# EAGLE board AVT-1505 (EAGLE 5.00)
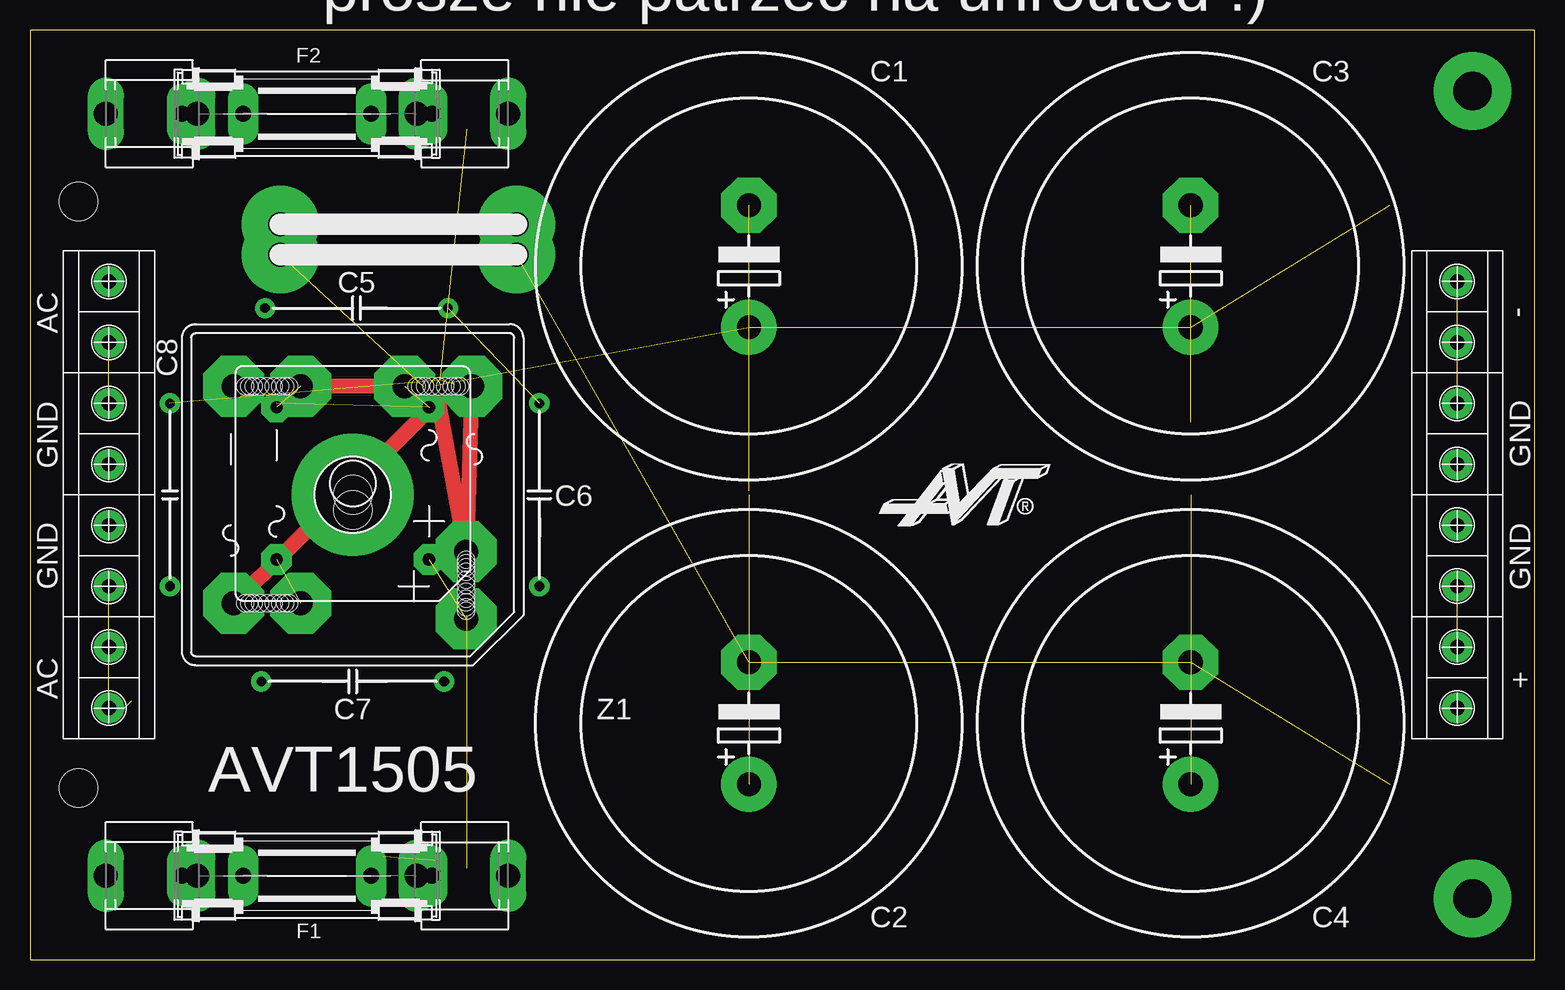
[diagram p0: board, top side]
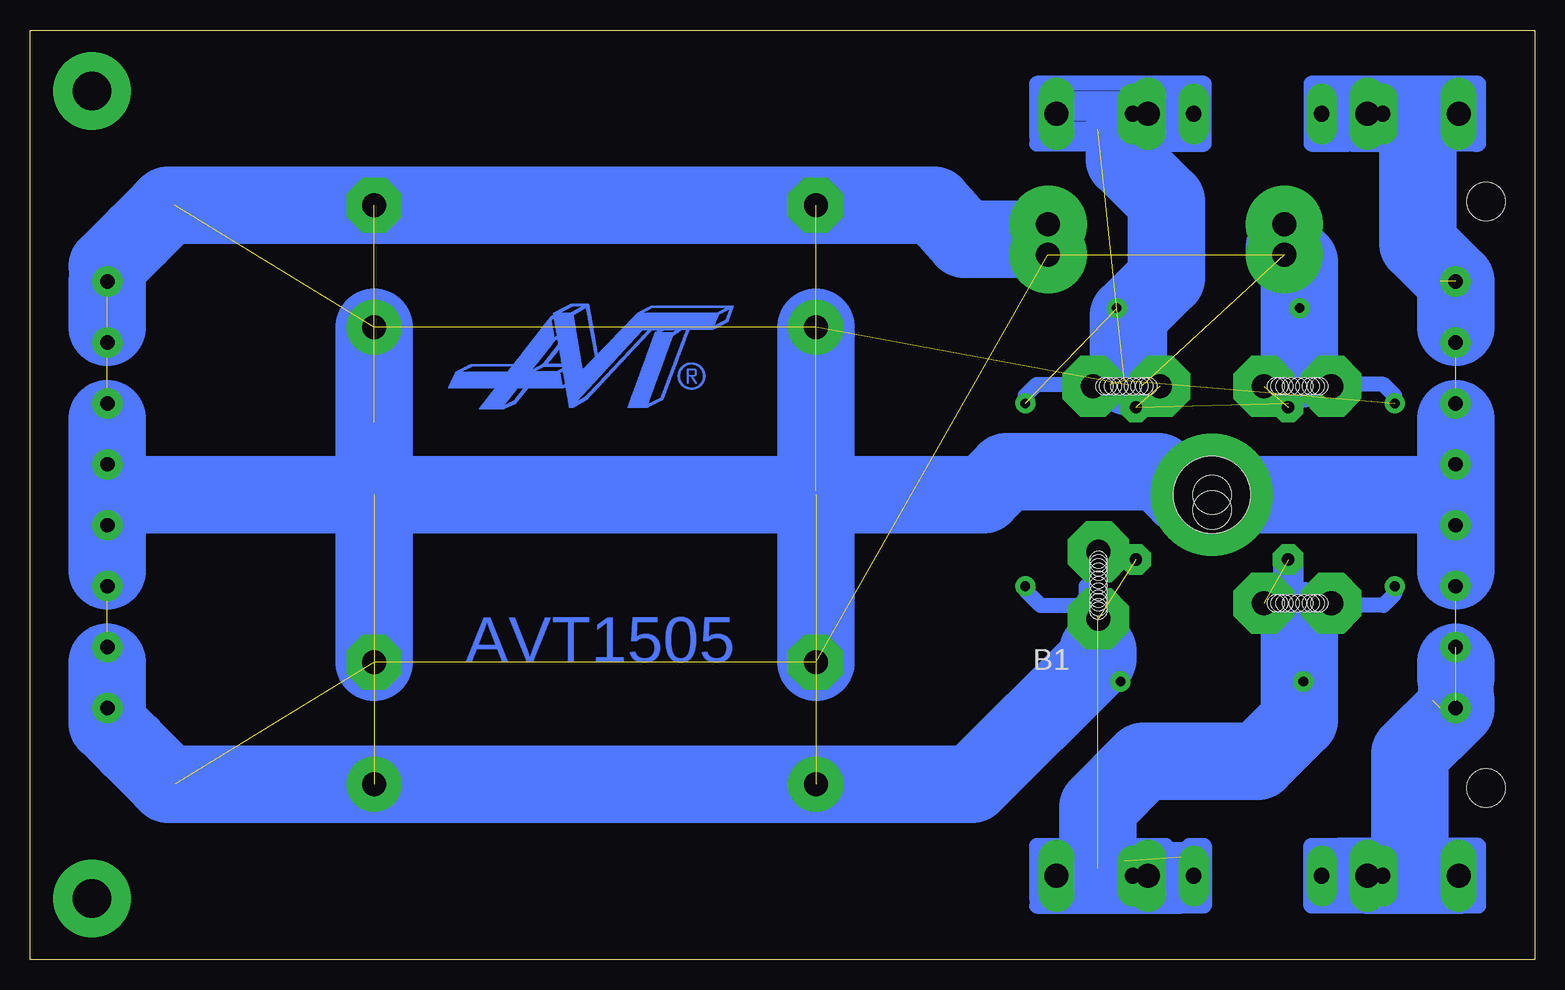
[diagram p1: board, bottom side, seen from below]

Size 125.43 x 77.46 mm. Coordinates in mm from the lower left corner, seen from the top.
Outline: 0,0 125.43,0 125.43,77.46 0,77.46 0,0
Copper layers (1*16): Top 0.035mm / dielectric 1.5mm / Bottom 0.035mm
Design rules "default": minimum track width 10mil, minimum drill 24mil, track to track 8mil, track to pad 8mil, pad to pad 8mil, via to via 8mil, smd to smd 8mil, copper to edge 40mil, drill to drill 8mil, minimum pad ring 10mil, minimum via ring 8mil, stop-mask expansion 4mil, vias tented up to drill 0mil, thermal gap 10mil
Holes 3.2 mm at 26.9,38.73 26.9,37.46 4.04,63.18 4.04,14.28

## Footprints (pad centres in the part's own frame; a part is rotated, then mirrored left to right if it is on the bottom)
B25A- = drill 2.007 pad 5.08 octagon: + -10.338,9.449; +1 -4.75,9.449; - 9.042,-4.343; -1 9.042,-9.931; AC1 9.042,4.343; AC1- 9.042,9.931; AC2 -9.042,-4.343; AC2- -9.042,-9.931 | hole 6.401: 0,0 | hole 1.4: -8.652,9.446; -6.429,9.446; -7.541,9.446; -9.366,9.446; -5.715,9.446; -6.032,9.446; -7.064,9.446; -8.096,9.446; -8.969,9.446; -5.397,9.446; -9.684,9.446; -9.049,-6.032; -9.049,-8.255; -9.049,-7.144; -9.049,-5.318; -9.049,-8.969; -9.049,-8.652; -9.049,-7.699; -9.049,-6.588; -9.049,-5.636; 9.049,-8.255; 9.049,-6.032; 9.049,-7.144; 9.049,-8.969; 9.049,-5.318; 9.049,-5.636; 9.049,-6.588; 9.049,-7.699; 9.049,-8.652; 9.049,6.032; 9.049,8.255; 9.049,7.144; 9.049,8.969; 9.049,5.318; 9.049,8.652; 9.049,7.699; 9.049,6.588; 9.049,5.636
GBPC8 = drill 1.016 pad 2.54 octagon: + 6.35,6.35; - -6.35,-6.35; AC1 -6.35,6.35; AC2 6.35,-6.35
EB35D = drill 2.007 pad 4.597 round: + -5.08,0 | drill 2.007 pad 4.597 octagon: - 5.08,0
SH32 = drill 2.007 long: 1A -16.764,0; 1B -9.144,0; 2A 9.144,0; 2B 16.764,0
SHK20L = drill 1.321 pad 2.54 long: 1A -10.414,0; 1B -5.334,0; 2A 10.414,0; 2B 5.334,0
ARK2 = drill 1.2 pad 2.54 round: 1 -2.54,0; 3 2.54,0 | drill 0.8 pad 2.54 round: 2 2.54,0

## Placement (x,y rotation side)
B1  [B25A-]  26.9,38.73 90 bottom
B2  [GBPC8]  26.9,39.68 270 top
C1  [EB35D]  59.92,57.78 90 top
C2  [EB35D]  59.92,19.68 90 top
C3  [EB35D]  96.75,57.78 90 top
C4  [EB35D]  96.75,19.68 90 top
F1  [SH32]  23.09,6.98 0 top
F2  [SH32]  23.09,70.48 0 top
F3  [SHK20L]  23.09,6.98 0 top
F4  [SHK20L]  23.09,70.48 0 top
U$1  ARK2  [ARK2]  6.58,33.65 90 top
U$2  ARK2  [ARK2]  6.58,43.81 90 top
U$5  ARK2  [ARK2]  6.58,23.49 90 top
U$6  ARK2  [ARK2]  6.58,53.97 90 top

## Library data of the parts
B1 B2 = rectifier
C1-C4 = rcl
F1-F4 = fuse
U$1 U$2 U$5 U$6 = ark2

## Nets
N$1: F1.1A U$5.1 U$5.2
N$2: F2.1A U$6.1 U$6.2
N$4: B1.AC1- F1.2A
N$10: B1.AC1 B2.AC1
N$11: B1.+1 B1.-1 C1.+ C1.- C2.+ C2.- C3.+ C3.- C4.+ C4.- U$1.1 U$1.2 U$2.1 U$2.2
N$22: B1.AC2 B2.AC2
N$23: B1.- B2.-
N$24: B1.+ B2.+
N$33: B1.AC2- F2.2A

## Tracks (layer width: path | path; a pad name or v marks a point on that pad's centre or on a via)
N$1  (1 unrouted)
  Bottom 1.27: F1.1A 9.76,6.98 9.76,7.62 10.39,8.25
  Bottom 6.452: 10.39,8.25 10.39,17.14 U$5.1 6.58,21.59
N$2  (4 unrouted)
  Bottom 1.27: F2.1A 6.58,70.48 6.58,69.84 9.76,69.84 | 4.04,55.24 4.04,56.51 | 4.04,55.24 4.04,53.97 U$6.1 | 5.31,46.35 arc-90 6.58,47.62 | 5.31,46.35 arc90 6.58,45.08 arc90 7.85,46.35 | 6.58,47.62 arc-90 7.85,46.35 | 5.31,46.35 arc-90 6.58,47.62 | 6.58,50.16 arc90 7.85,51.43 arc90 6.58,52.7 arc90 5.31,51.43 arc90 6.58,50.16 | 7.85,31.11 arc-90 6.58,29.84 arc-90 5.31,31.11 | 5.31,31.11 arc-90 6.58,32.38 arc-90 7.85,31.11 | 6.58,24.76 arc-90 5.31,26.03 arc-90 6.58,27.3 | 6.58,24.76 arc90 7.85,26.03 arc90 6.58,27.3 | 4.04,55.24 4.04,52.7 6.58,50.16 | 6.58,50.16 9.12,52.7 9.12,55.88 | 6.58,27.3 4.04,24.76 4.04,20.32 8.49,20.32 8.49,21.59 9.12,22.22 9.12,24.76 6.58,27.3 | 6.58,27.3 6.58,26.03 4.68,24.12 8.49,24.12 7.85,24.76 6.58,24.76 | 6.58,24.76 4.68,24.76 | 5.31,31.11 5.95,31.11 | 5.31,31.11 5.31,46.35 | 5.31,46.35 7.85,46.35 | 7.85,46.35 7.85,31.11 | 7.85,56.51 arc90 6.58,57.78 arc90 5.31,56.51 arc90 6.58,55.24 arc90 7.85,56.51 | 5.31,20.95 arc90 6.58,19.68 arc90 7.85,20.95 arc90 6.58,22.22 arc90 5.31,20.95
  Bottom 6.452: 9.76,69.84 9.76,59.69 U$6.2 6.58,52.7 | 6.58,24.76 6.58,23.49 | 6.58,32.38 6.58,45.08
N$3
  Bottom 1.27: 5.31,72.38 14.2,72.38 14.2,71.11 | 14.2,71.11 14.2,71.75 | 14.2,69.21 14.2,71.11 | 14.2,69.21 14.2,68.57 | 14.2,69.21 14.2,70.48 13.57,70.48 | 14.2,69.21 13.57,69.21 13.57,70.48 | 13.57,70.48 13.57,71.11 | 13.57,70.48 13.57,69.84 | 13.57,70.48 13.57,71.75 14.84,71.75 14.84,67.94 15.31,67.94 | 15.31,67.94 15.47,67.94 | 15.47,67.94 15.47,73.02 13.57,73.02 | 13.57,73.02 4.68,73.02 4.68,67.94 5.07,67.94 | 5.07,67.94 6.58,67.94 | 4.99,68.1 5.07,68.1 5.07,67.94 | 5.07,67.94 15.31,67.94 | 15.31,67.94 12.77,67.94 12.77,71.99 5.55,71.99 5.55,71.27 7.06,71.27 7.06,68.73 | 13.57,73.02 18.65,73.02 18.65,67.94 15.47,67.94 | 15.47,67.94 16.42,67.94 16.42,72.7 17.38,72.7 | 17.69,72.7 17.38,72.7 | 17.38,72.7 17.38,68.26
N$4  (via drill 0.6)  (1 unrouted)
  Top 1.27: B1.AC1- v36.27,29.69
  Bottom 1.27: F1.2A 35.79,6.98 36.43,7.62 | 36.43,29.84 v36.27,29.69 36.43,29.2 36.43,28.57
  Bottom 6.452: 36.43,7.62 36.43,12.7 32.62,16.5 23.09,16.5 19.6,20 19.6,28.25
N$6
  Bottom 1.27: 32.62,73.02 31.35,73.02 | 32.62,73.02 41.51,73.02 41.51,71.75 | 41.51,69.21 41.51,70.48 | 41.51,68.57 41.51,69.21 | 41.51,68.57 41.51,67.94 34.2,67.94 31.03,67.94 | 31.03,67.94 30.71,67.94 30.71,68.57 | 30.71,69.21 30.71,70.48 | 30.71,73.02 30.71,71.75 | 30.71,71.75 41.51,71.75 | 41.51,70.48 41.51,71.75 | 30.71,70.48 41.51,70.48 | 30.71,70.48 30.71,71.75 | 30.71,73.02 32.62,73.02 | 30.71,69.21 30.71,73.02 | 30.71,69.21 41.51,69.21 | 30.71,68.57 30.71,69.21 | 30.71,68.57 31.98,68.57 | 31.98,68.57 41.51,68.57 | 31.98,68.57 32.3,68.57 32.3,68.26 31.03,68.26 31.03,67.94 | 31.03,67.94 27.54,67.94 27.54,73.02 30.71,73.02 | 30.71,73.02 29.76,73.02 29.76,68.26 28.81,68.26 | 28.49,68.26 28.81,68.26 | 28.81,68.26 28.81,72.38
  Bottom 6.452: 33.89,48.57 33.89,53.65 30.71,56.83 30.71,63.18 34.2,66.67 34.2,67.94
N$7
  Bottom 1.27: 7.85,72.38 6.58,72.38 6.58,69.21
N$9  (via drill 0.8 pad 1.68)
  other vias: 19.28,23.17
N$10  (2 unrouted)
N$11  (via drill 0.6, 1.2 pad 2.54, 2 pad 6.45, 3.2 pad 10.16)  (13 unrouted)
  Top 1.27: B1.+1 v33.81,47.86 | v32.77,47.79 B1.-1
  Bottom 1.27: 6.58,38.73 9.12,38.73 | 7.85,41.27 U$2.1 5.95,40.63 5.95,36.19 | 8.49,36.19 9.76,36.19 | 8.49,36.19 10.39,36.19 | 7.85,36.19 8.49,36.19 | 7.85,41.27 5.31,41.27 | 7.85,41.27 9.12,41.27 | 5.31,36.19 5.31,41.27 | U$1.2 5.95,36.19 | U$1.2 7.85,36.19 | 5.31,41.27 arc-90 6.58,42.54 | 7.85,41.27 arc90 6.58,42.54 | 5.95,36.19 5.31,36.19 | 5.31,36.19 arc90 6.58,34.92 arc90 7.85,36.19 | U$1.1 U$1.2 | 6.58,42.54 U$2.2
  Bottom 2.54: U$1.2 6.58,38.73 U$2.1
  Bottom 3.81: 118.98,52.7 v118.98,51.43 | v118.98,56.51 118.98,57.78 118.98,59.05 | v118.98,26.03 v118.98,20.95 118.98,19.68 118.98,18.41
  Bottom 6.452: 113.37,62.86 arc-45 114.27,62.49 116.44,60.32 | 116.44,60.32 118.98,57.78 | v118.98,56.51 118.98,52.7 | 96.75,38.73 96.75,42.22 | 59.92,38.73 59.92,39.05 | 59.92,38.73 96.75,38.73 | 58.97,38.73 45.95,38.73 44.05,40.63 31.35,40.63 29.44,38.73 v26.9,38.73 9.12,38.73 | 58.97,38.73 59.92,38.73 | 96.75,38.73 111.99,38.73 | 111.99,38.73 115.17,38.73 | 111.99,38.73 117.71,38.73 | 58.97,38.73 59.6,39.37 59.92,39.05 | 113.37,14.6 arc45 114.27,14.97 117.07,17.77 | 117.07,17.77 118.98,19.68 | 59.92,39.05 59.92,33.33 | 59.92,33.33 C2.- | 87.86,14.6 C2.+ 51.35,14.6 | 87.86,14.6 89.45,14.6 | 87.86,14.6 113.9,14.6 117.07,17.77 | C4.- 96.75,42.22 | 96.75,42.22 96.75,44.76 | C1.+ 59.92,33.33 | C3.+ 96.75,42.22 | 116.44,60.32 113.9,62.86 C3.- C1.- 56.75,62.86 | 56.75,62.86 55.16,62.86 | 42.14,60 47.54,60 50.08,62.86 56.75,62.86
  other vias: 20.87,58.73 40.55,58.73 20.87,61.27 40.55,61.27
N$12  (via drill 1.2 pad 2.54)
  Bottom 3.81: v118.98,36.19 v118.98,41.27
N$13  (2 unrouted)
  Bottom 1.27: 117.71,56.51 arc-90 118.98,57.78 | 117.71,56.51 arc-90 118.98,57.78 | 117.71,56.51 arc90 118.98,55.24 arc90 120.25,56.51 arc90 118.98,57.78 | 117.71,46.35 arc-90 118.98,47.62 arc-90 120.25,46.35 arc-90 118.98,45.08 arc-90 117.71,46.35 | 117.71,51.43 arc-90 118.98,52.7 arc-90 120.25,51.43 arc-90 118.98,50.16 arc-90 117.71,51.43
N$15
  Bottom 1.27: 118.34,41.27 arc-90 118.98,42.54 arc-90 120.25,41.27 arc-90 118.98,40 arc-90 118.34,41.27
N$17
  Bottom 1.27: 113.9,38.73 arc-90 112.63,40 arc-90 113.9,38.73
N$18  (1 unrouted)
  Bottom 1.27: 117.71,31.11 arc-90 118.98,32.38 arc-90 120.25,31.11 arc-90 118.98,29.84 arc-90 117.71,31.11 | 117.71,20.95 arc-90 118.98,22.22 arc-90 120.25,20.95 arc-90 118.98,19.68 arc-90 117.71,20.95 | 118.98,24.76 arc90 120.25,26.03 arc90 118.98,27.3 arc90 117.71,26.03 arc90 118.98,24.76
  Bottom 6.452: 118.98,19.68 118.98,24.76
N$19
  Bottom 1.27: 5.95,68.57 5.95,71.11
N$20
  Bottom 1.27: 5.15,6.35 5.87,6.35 5.87,5.47 14.2,5.47 14.2,5.55 | 5.95,9.52 5.31,9.52 | 5.95,9.52 15.47,9.52 | 15.47,9.52 15.47,4.44 15.15,4.44 | 14.2,4.44 15.15,4.44 | 14.2,4.44 4.68,4.44 4.68,9.52 5.95,9.52 | 5.95,9.52 14.2,9.52 14.2,8.25 | 14.2,8.25 14.2,6.98 | 14.2,4.44 5.95,4.44 5.95,8.25 | 5.95,9.52 5.95,8.25 | 5.95,8.25 14.2,8.25 | 14.2,8.25 6.58,8.25 6.58,6.98 | 6.58,6.35 6.58,5.08 | 14.2,4.44 14.2,5.55 | 14.2,5.55 14.2,6.35 | 14.2,6.35 14.2,6.98 | 14.2,6.98 6.58,6.98 | 6.58,6.35 6.58,6.98 | 14.2,6.35 6.58,6.35 | 14.2,5.55 14.52,5.55 14.52,7.22 | 15.15,4.44 17.38,4.44 | 17.38,4.44 18.65,4.44 18.65,9.52 15.47,9.52 | 15.47,9.52 16.42,9.52 16.42,4.76 17.38,4.76 17.38,4.44 | 17.38,4.44 17.38,8.88
N$21  (via drill 1.2 pad 2.54)
  Bottom 3.81: v118.98,31.11 118.98,32.38 | 118.98,45.08 v118.98,46.35
  Bottom 6.452: 118.98,32.38 118.98,45.08
N$22  (1 unrouted)
  Bottom 2.54: 20.23,29.2 20.23,29.84 20.55,30.16 B2.AC2
N$23  (1 unrouted)
N$24  (1 unrouted)
N$25  (1 unrouted)
  Bottom 0.406: 33.57,8.57 30.08,8.57 29.44,7.93
  Bottom 1.27: 31.03,9.2 28.81,9.2 28.81,9.52 27.54,9.52 27.54,4.44 31.03,4.44 | 41.51,4.44 31.35,4.44 | 41.51,5.08 41.51,9.52 30.71,9.52 30.71,4.44 31.03,4.44 | 41.51,4.44 31.03,4.44 | 41.51,5.08 41.51,4.44 | 41.51,5.08 31.35,5.08 31.35,8.88 40.87,8.88 40.87,5.71 32.62,5.71 32.62,8.25 34.2,8.25 40.24,8.25 40.24,6.98 31.98,6.98 | 31.03,4.44 29.44,4.44 29.44,7.93 29.44,8.25 28.81,8.25 28.81,8.88 28.49,8.88 28.49,5.08
N$26  (via drill 0.8 pad 1.68)
  other vias: 34.52,23.17
N$27  (via drill 0.8 pad 1.68)
  Bottom 1.27: v42.46,31.11 42.46,30.79 41.19,29.52 37.7,29.52 37.7,29.84 37.38,30.16 37.38,31.11
N$28  (via drill 3.2 pad 6.45)
  other vias: 120.25,72.38
N$29  (via drill 3.2 pad 6.45)
  other vias: 120.25,5.08
N$30  (via drill 0.8 pad 1.68)  (1 unrouted)
  Bottom 1.27: v42.46,46.35 42.46,46.98 41.51,47.94 35.79,47.94
  other vias: 34.84,54.29
N$32  (via drill 0.8 pad 1.68)
  other vias: 19.6,54.29
N$33  (via drill 0.6, 0.8 pad 1.68)  (3 unrouted)
  Top 1.27: B1.AC2- v35.41,47.94
  Bottom 1.27: 17.06,47.94 12.61,47.94 11.66,46.98 v11.66,46.35 | F2.2A 36.43,69.21 37.06,70.48
N$34  (via drill 0.8 pad 1.68)
  Bottom 1.27: v11.66,31.11 11.66,30.48 12.61,29.52 17.06,29.52
S$1
  Bottom 6.452: 51.35,14.6 46.9,14.6 36.43,25.08 36.43,25.71
S$3
  Bottom 6.452: 20.87,59.37 19.6,58.1 19.6,49.21
(copper drawn outside any net)
  shapes: Bottom area x4432

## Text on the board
Bottom: AVT1505
tPlace: Sciezki bez maski pocynowane | prosze nie patrzec na unrouted :) | AC | C5 | - | C8 | GND | GND | C6 | GND | GND | AC | + | C7 | Z1 | AVT1505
